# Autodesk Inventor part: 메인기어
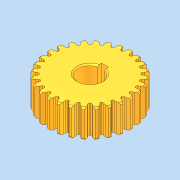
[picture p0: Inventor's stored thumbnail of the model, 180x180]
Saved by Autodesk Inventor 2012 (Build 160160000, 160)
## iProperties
Company: 한국ATC센터
Created: 2014-12
Part Number: 메인기어
Document SubType Name: Modeling
Designer: KYOUNG IL JANG
Density: 1 g/cm^3
Mass: 43.883 g
Surface Area: 122.661 cm^2
Volume: 43.883 cm^3
Material: 기본값
Author: KYOUNG IL JANG
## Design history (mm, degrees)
sketch "스케치1"
  geometry: C1 r 25.5 at (0, 0); A1 r 1.064 centre (-2.94, 26.392) between (-2.696, 25.357) and (-1.877, 26.361); A2 r 6.991 centre (5.094, 25.835) between (-1.626, 27.763) and (-1.877, 26.361); A3 r 11.864 centre (9.774, 24.478) between (-0.731, 29.991) and (-1.626, 27.763); A4 r 1.064 centre (2.94, 26.392) between (1.877, 26.361) and (2.696, 25.357); A5 r 6.991 centre (-5.094, 25.835) between (1.877, 26.361) and (1.626, 27.763); A6 r 11.864 centre (-9.774, 24.478) between (1.626, 27.763) and (0.731, 29.991); A7 r 25.5 centre (0, 0) between (2.696, 25.357) and (-2.696, 25.357); A8 r 30 centre (0, 0) between (0.731, 29.991) and (-0.731, 29.991); 1 further point
  constraints: 16 point on circle, 9 centre point, 2 coincident, 1 concentric
extrude "돌출1" new body sketch "스케치1" stored distance "d0" = 20; taper "d1" = 0 deg
extrude "돌출2" join sketch "스케치1" stored distance "d2" = 20; taper "d3" = 0 deg
chamfer "모따기1" distance "d4" = 1; stored, may be unused: second distance "d5" = 2, angle "d6" = 45 deg
hole "구멍1" diameter "d12" = 17; stored, may be unused: countersink angle "d16" = 90 deg, drill point angle "d18" = 118 deg; dims "d10" = 10, "d11" = 10, "d13" = 6, "d14" = 4, "d15" = 2, "d17" = 8
sketch "스케치2"
  geometry: L1 (-2.5, 8.124)-(-2.5, 10.8); L2 (-2.5, 10.8)-(2.5, 10.8); L3 (2.5, 10.8)-(2.5, 8.124); A1 r 8.5 centre (0, 0) between (-2.5, 8.124) and (2.5, 8.124) reference; 1 further point
  constraints: 6 end point, 2 parallel, 2 point on circle, 1 perpendicular, 1 vertical
  dimensions: "d19" = 5 distance of L1.end L2.end; "d20" = 2.3 distance edge to line of A1 L2
extrude "돌출3" cut sketch "스케치2" stored distance "d21" = 20; taper "d22" = 0 deg
chamfer "모따기2" distance "d23" = 1; stored, may be unused: second distance "d24" = 2, angle "d25" = 45 deg
node "솔리드1"
pattern_circular "원형 패턴1" dims angle "d8" = 360 deg
